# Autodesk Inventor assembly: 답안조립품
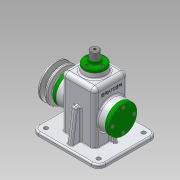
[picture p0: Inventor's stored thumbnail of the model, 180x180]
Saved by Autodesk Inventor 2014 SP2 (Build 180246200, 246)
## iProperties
Created: 2016-08
Part Number: 답안조립품
Document SubType Name: Assembly
Designer: user
Author: user
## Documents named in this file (19)
- C:\Users\user\Desktop\460820V1002\답안조립품.iam
- C:\Users\user\Desktop\460820V1002\본체.ipt
- C:\Users\user\Desktop\460820V1002\뒤커버.ipt
- C:\Users\user\Desktop\460820V1002\베어링 15 x 35 x 11.ipt
- C:\Users\user\Desktop\460820V1002\볼트 M4 x 10.ipt
- C:\Users\user\Desktop\460820V1002\앞커버.ipt
- C:\Users\user\Desktop\460820V1002\오일실 15 25 7.ipt
- C:\Users\user\Desktop\460820V1002\멈춤링 15 x 1.ipt
- C:\Users\user\Desktop\460820V1002\볼트 M3 x 8.ipt
- C:\Users\user\Desktop\460820V1002\상부부시.ipt
- C:\Users\user\Desktop\460820V1002\V-벨트풀리.ipt
- C:\Users\user\Desktop\460820V1002\키 5 x 5 x 14.ipt
- C:\Users\user\Desktop\460820V1002\편심축.ipt
- C:\Users\user\Desktop\460820V1002\볼트 M6 x 12.ipt
- C:\Users\user\Desktop\460820V1002\와셔.ipt
- C:\Users\user\Desktop\460820V1002\고정핀.ipt
- C:\Users\user\Desktop\460820V1002\링크.ipt
- C:\Users\user\Desktop\460820V1002\멈춤링 6 x 5.ipt
- C:\Users\user\Desktop\460820V1002\슬라이드바.ipt
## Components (15 placed, 5 different names)
1. V-벨트풀리:1 — 각도:1
2. ISO 4018 M6 x 12:1 — 강체:4
3. 고정핀:1
4. ISO 4762 M4 x 10:1 — 강체:2
5. ISO 4762 M4 x 10:2 — 강체:1
6. ISO 4762 M4 x 10:3
7. ISO 4762 M4 x 10:4
8. ISO 4762 M4 x 10:5
9. ISO 4762 M4 x 10:6
10. ISO 4762 M4 x 10:7
11. ISO 4762 M4 x 10:8
12. ISO 4762 M3 x 8:1 — 강체:3
13. ISO 4762 M3 x 8:2
14. ISO 4762 M3 x 8:3
15. ISO 4762 M3 x 8:4
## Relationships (5: WeldJoint 4, Angle 1)
- 강체:1 [WeldJoint]: ISO 4762 M4 x 10:2
- 강체:2 [WeldJoint]: ISO 4762 M4 x 10:1
- 강체:3 [WeldJoint]: ISO 4762 M3 x 8:1
- 강체:4 [WeldJoint]: ISO 4018 M6 x 12:1
- 각도:1 [Angle]: V-벨트풀리:1
